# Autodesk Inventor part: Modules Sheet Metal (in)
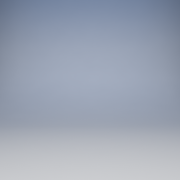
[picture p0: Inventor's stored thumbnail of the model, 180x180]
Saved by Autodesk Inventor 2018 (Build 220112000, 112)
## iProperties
Created: 2014-08
Part Number: Modules Sheet Metal (in)
Material: Generic
Document SubType Name: Sheet Metal
Designer: Wally
Density: 1 g/cm^3
Sheet Metal Rule: Default
Appearance: Default
Author: Wally
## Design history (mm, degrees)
node "Sketch1"
other parameters: "Thickness" = 3.048, "BendRadius" = 3.048 (= Thickness), "BendReliefWidth" = 3.048 (= Thickness), "BendReliefDepth" = 1.524 (= 0.5 x Thickness), "CornerReliefSize" = 12.192 (= 4 x Thickness), "SeamGap" = 0.01, "MinimumRemnant" = 6.096 (= 2 x Thickness), "TransitionRadius" = 3.048 (= BendRadius), "JacobiRadiusSize" = 3.048 (= Thickness), "GapSize" = 3.048 (= Thickness)
